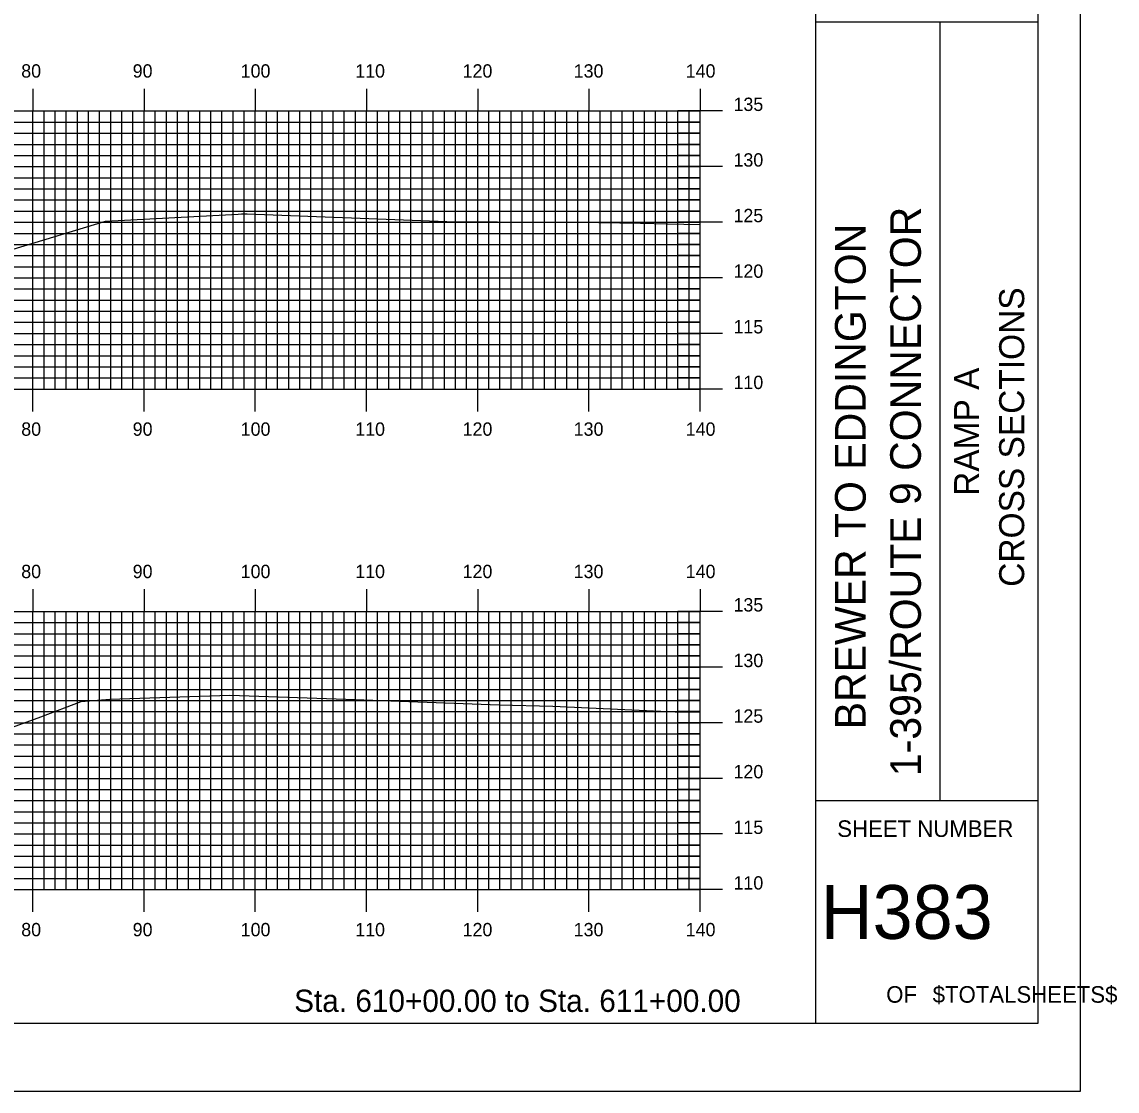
# Model space of a CAD drawing. Extents: x 843356 to 843699, y 363538 to 363758.
# Drawn here: x 843600.4 to 843698.9, y 363537.6 to 363633.7 of the extents above; entities that cross this region are included whole.
import ezdxf

# ---------------------------------------------------------------- set-up
doc = ezdxf.new("R2010")
doc.units = 0
for name, color, linetype in [('BORDER', 7, 'Continuous'), ('H_V ANNOTATION', 7, 'Continuous'), ('MAJOR', 7, 'Continuous'), ('MINOR', 7, 'Continuous'), ('PLOT BOUNDARY', 7, 'Continuous'), ('S_Roadway_Centerline', 7, 'Continuous')]:
    doc.layers.add(name, color=color, linetype=linetype)

msp = doc.modelspace()

# ---------------------------------------------------------------- linework, layer by layer
at = {"layer": 'BORDER'}
for p, q in [((843671.824, 363543.721), (843671.824, 363753.721)), ((843671.824, 363633.727), (843691.824, 363633.727)), ((843683.006, 363563.727), (843683.006, 363633.727)), ((843671.824, 363563.727), (843691.824, 363563.727))]:
    msp.add_line(p, q, dxfattribs=at)
msp.add_lwpolyline([(843371.824, 363543.721), (843691.824, 363543.721), (843691.824, 363753.721), (843371.824, 363753.721)], close=True, dxfattribs=at)
at = {"layer": 'MAJOR'}
for p, q in [((843601.424, 363627.725), (843601.424, 363625.721)), ((843611.424, 363627.725), (843611.424, 363625.721)), ((843621.424, 363627.725), (843621.424, 363625.721)), ((843631.424, 363627.725), (843631.424, 363625.721)), ((843641.424, 363627.725), (843641.424, 363625.721)), ((843651.424, 363627.725), (843651.424, 363625.721)), ((843661.424, 363627.725), (843661.424, 363625.721)), ((843381.424, 363625.721), (843661.424, 363625.721)), ((843381.424, 363625.721), (843661.424, 363625.721)), ((843601.424, 363600.721), (843601.424, 363625.721)), ((843611.424, 363600.721), (843611.424, 363625.721)), ((843621.424, 363600.721), (843621.424, 363625.721)), ((843631.424, 363600.721), (843631.424, 363625.721)), ((843641.424, 363600.721), (843641.424, 363625.721)), ((843651.424, 363600.721), (843651.424, 363625.721)), ((843663.428, 363625.721), (843659.42, 363625.721)), ((843661.424, 363600.721), (843661.424, 363625.721)), ((843661.424, 363600.721), (843661.424, 363625.721)), ((843381.424, 363620.721), (843661.424, 363620.721)), ((843663.428, 363620.721), (843659.42, 363620.721)), ((843381.424, 363615.721), (843661.424, 363615.721)), ((843663.428, 363615.721), (843659.42, 363615.721)), ((843381.424, 363610.721), (843661.424, 363610.721)), ((843663.428, 363610.721), (843659.42, 363610.721)), ((843381.424, 363605.721), (843661.424, 363605.721)), ((843663.428, 363605.721), (843659.42, 363605.721)), ((843381.424, 363600.721), (843661.424, 363600.721)), ((843381.424, 363600.721), (843661.424, 363600.721)), ((843601.424, 363598.717), (843601.424, 363600.721)), ((843611.424, 363598.717), (843611.424, 363600.721)), ((843621.424, 363598.717), (843621.424, 363600.721)), ((843631.424, 363598.717), (843631.424, 363600.721)), ((843641.424, 363598.717), (843641.424, 363600.721)), ((843651.424, 363598.717), (843651.424, 363600.721)), ((843663.428, 363600.721), (843659.42, 363600.721)), ((843661.424, 363598.717), (843661.424, 363600.721)), ((843601.424, 363582.725), (843601.424, 363580.721)), ((843611.424, 363582.725), (843611.424, 363580.721)), ((843621.424, 363582.725), (843621.424, 363580.721)), ((843631.424, 363582.725), (843631.424, 363580.721)), ((843641.424, 363582.725), (843641.424, 363580.721)), ((843651.424, 363582.725), (843651.424, 363580.721)), ((843661.424, 363582.725), (843661.424, 363580.721)), ((843381.424, 363580.721), (843661.424, 363580.721)), ((843381.424, 363580.721), (843661.424, 363580.721)), ((843601.424, 363555.721), (843601.424, 363580.721)), ((843611.424, 363555.721), (843611.424, 363580.721)), ((843621.424, 363555.721), (843621.424, 363580.721)), ((843631.424, 363555.721), (843631.424, 363580.721)), ((843641.424, 363555.721), (843641.424, 363580.721)), ((843651.424, 363555.721), (843651.424, 363580.721)), ((843663.428, 363580.721), (843659.42, 363580.721)), ((843661.424, 363555.721), (843661.424, 363580.721)), ((843661.424, 363555.721), (843661.424, 363580.721)), ((843381.424, 363575.721), (843661.424, 363575.721)), ((843663.428, 363575.721), (843659.42, 363575.721)), ((843381.424, 363570.721), (843661.424, 363570.721)), ((843663.428, 363570.721), (843659.42, 363570.721)), ((843381.424, 363565.721), (843661.424, 363565.721)), ((843663.428, 363565.721), (843659.42, 363565.721)), ((843381.424, 363560.721), (843661.424, 363560.721)), ((843663.428, 363560.721), (843659.42, 363560.721)), ((843381.424, 363555.721), (843661.424, 363555.721)), ((843381.424, 363555.721), (843661.424, 363555.721)), ((843601.424, 363553.717), (843601.424, 363555.721)), ((843611.424, 363553.717), (843611.424, 363555.721)), ((843621.424, 363553.717), (843621.424, 363555.721)), ((843631.424, 363553.717), (843631.424, 363555.721)), ((843641.424, 363553.717), (843641.424, 363555.721)), ((843651.424, 363553.717), (843651.424, 363555.721)), ((843663.428, 363555.721), (843659.42, 363555.721)), ((843661.424, 363553.717), (843661.424, 363555.721))]:
    msp.add_line(p, q, dxfattribs=at)
at = {"layer": 'MINOR'}
for p, q in [((843602.424, 363600.721), (843602.424, 363625.721)), ((843603.424, 363600.721), (843603.424, 363625.721)), ((843604.424, 363600.721), (843604.424, 363625.721)), ((843605.424, 363600.721), (843605.424, 363625.721)), ((843606.424, 363600.721), (843606.424, 363625.721)), ((843607.424, 363600.721), (843607.424, 363625.721)), ((843608.424, 363600.721), (843608.424, 363625.721)), ((843609.424, 363600.721), (843609.424, 363625.721)), ((843610.424, 363600.721), (843610.424, 363625.721)), ((843612.424, 363600.721), (843612.424, 363625.721)), ((843613.424, 363600.721), (843613.424, 363625.721)), ((843614.424, 363600.721), (843614.424, 363625.721)), ((843615.424, 363600.721), (843615.424, 363625.721)), ((843616.424, 363600.721), (843616.424, 363625.721)), ((843617.424, 363600.721), (843617.424, 363625.721)), ((843618.424, 363600.721), (843618.424, 363625.721)), ((843619.424, 363600.721), (843619.424, 363625.721)), ((843620.424, 363600.721), (843620.424, 363625.721)), ((843622.424, 363600.721), (843622.424, 363625.721)), ((843623.424, 363600.721), (843623.424, 363625.721)), ((843624.424, 363600.721), (843624.424, 363625.721)), ((843625.424, 363600.721), (843625.424, 363625.721)), ((843626.424, 363600.721), (843626.424, 363625.721)), ((843627.424, 363600.721), (843627.424, 363625.721)), ((843628.424, 363600.721), (843628.424, 363625.721)), ((843629.424, 363600.721), (843629.424, 363625.721)), ((843630.424, 363600.721), (843630.424, 363625.721)), ((843632.424, 363600.721), (843632.424, 363625.721)), ((843633.424, 363600.721), (843633.424, 363625.721)), ((843634.424, 363600.721), (843634.424, 363625.721)), ((843635.424, 363600.721), (843635.424, 363625.721)), ((843636.424, 363600.721), (843636.424, 363625.721)), ((843637.424, 363600.721), (843637.424, 363625.721)), ((843638.424, 363600.721), (843638.424, 363625.721)), ((843639.424, 363600.721), (843639.424, 363625.721)), ((843640.424, 363600.721), (843640.424, 363625.721)), ((843642.424, 363600.721), (843642.424, 363625.721)), ((843643.424, 363600.721), (843643.424, 363625.721)), ((843644.424, 363600.721), (843644.424, 363625.721)), ((843645.424, 363600.721), (843645.424, 363625.721)), ((843646.424, 363600.721), (843646.424, 363625.721)), ((843647.424, 363600.721), (843647.424, 363625.721)), ((843648.424, 363600.721), (843648.424, 363625.721)), ((843649.424, 363600.721), (843649.424, 363625.721)), ((843650.424, 363600.721), (843650.424, 363625.721)), ((843652.424, 363600.721), (843652.424, 363625.721)), ((843653.424, 363600.721), (843653.424, 363625.721)), ((843654.424, 363600.721), (843654.424, 363625.721)), ((843655.424, 363600.721), (843655.424, 363625.721)), ((843656.424, 363600.721), (843656.424, 363625.721)), ((843657.424, 363600.721), (843657.424, 363625.721)), ((843658.424, 363600.721), (843658.424, 363625.721)), ((843659.424, 363600.721), (843659.424, 363625.721)), ((843660.424, 363600.721), (843660.424, 363625.721)), ((843381.424, 363624.721), (843661.424, 363624.721)), ((843661.424, 363624.721), (843659.42, 363624.721)), ((843381.424, 363623.721), (843661.424, 363623.721)), ((843661.424, 363623.721), (843659.42, 363623.721)), ((843381.424, 363622.721), (843661.424, 363622.721)), ((843661.424, 363622.721), (843659.42, 363622.721)), ((843381.424, 363621.721), (843661.424, 363621.721)), ((843661.424, 363621.721), (843659.42, 363621.721)), ((843381.424, 363619.721), (843661.424, 363619.721)), ((843661.424, 363619.721), (843659.42, 363619.721)), ((843381.424, 363618.721), (843661.424, 363618.721)), ((843661.424, 363618.721), (843659.42, 363618.721)), ((843381.424, 363617.721), (843661.424, 363617.721)), ((843661.424, 363617.721), (843659.42, 363617.721)), ((843381.424, 363616.721), (843661.424, 363616.721)), ((843661.424, 363616.721), (843659.42, 363616.721)), ((843381.424, 363614.721), (843661.424, 363614.721)), ((843661.424, 363614.721), (843659.42, 363614.721)), ((843381.424, 363613.721), (843661.424, 363613.721)), ((843661.424, 363613.721), (843659.42, 363613.721)), ((843381.424, 363612.721), (843661.424, 363612.721)), ((843661.424, 363612.721), (843659.42, 363612.721)), ((843381.424, 363611.721), (843661.424, 363611.721)), ((843661.424, 363611.721), (843659.42, 363611.721)), ((843381.424, 363609.721), (843661.424, 363609.721)), ((843661.424, 363609.721), (843659.42, 363609.721)), ((843381.424, 363608.721), (843661.424, 363608.721)), ((843661.424, 363608.721), (843659.42, 363608.721)), ((843381.424, 363607.721), (843661.424, 363607.721)), ((843661.424, 363607.721), (843659.42, 363607.721)), ((843381.424, 363606.721), (843661.424, 363606.721)), ((843661.424, 363606.721), (843659.42, 363606.721)), ((843381.424, 363604.721), (843661.424, 363604.721)), ((843661.424, 363604.721), (843659.42, 363604.721)), ((843381.424, 363603.721), (843661.424, 363603.721)), ((843661.424, 363603.721), (843659.42, 363603.721)), ((843381.424, 363602.721), (843661.424, 363602.721)), ((843661.424, 363602.721), (843659.42, 363602.721)), ((843381.424, 363601.721), (843661.424, 363601.721)), ((843661.424, 363601.721), (843659.42, 363601.721)), ((843602.424, 363555.721), (843602.424, 363580.721)), ((843603.424, 363555.721), (843603.424, 363580.721)), ((843604.424, 363555.721), (843604.424, 363580.721)), ((843605.424, 363555.721), (843605.424, 363580.721)), ((843606.424, 363555.721), (843606.424, 363580.721)), ((843607.424, 363555.721), (843607.424, 363580.721)), ((843608.424, 363555.721), (843608.424, 363580.721)), ((843609.424, 363555.721), (843609.424, 363580.721)), ((843610.424, 363555.721), (843610.424, 363580.721)), ((843612.424, 363555.721), (843612.424, 363580.721)), ((843613.424, 363555.721), (843613.424, 363580.721)), ((843614.424, 363555.721), (843614.424, 363580.721)), ((843615.424, 363555.721), (843615.424, 363580.721)), ((843616.424, 363555.721), (843616.424, 363580.721)), ((843617.424, 363555.721), (843617.424, 363580.721)), ((843618.424, 363555.721), (843618.424, 363580.721)), ((843619.424, 363555.721), (843619.424, 363580.721)), ((843620.424, 363555.721), (843620.424, 363580.721)), ((843622.424, 363555.721), (843622.424, 363580.721)), ((843623.424, 363555.721), (843623.424, 363580.721)), ((843624.424, 363555.721), (843624.424, 363580.721)), ((843625.424, 363555.721), (843625.424, 363580.721)), ((843626.424, 363555.721), (843626.424, 363580.721)), ((843627.424, 363555.721), (843627.424, 363580.721)), ((843628.424, 363555.721), (843628.424, 363580.721)), ((843629.424, 363555.721), (843629.424, 363580.721)), ((843630.424, 363555.721), (843630.424, 363580.721)), ((843632.424, 363555.721), (843632.424, 363580.721)), ((843633.424, 363555.721), (843633.424, 363580.721)), ((843634.424, 363555.721), (843634.424, 363580.721)), ((843635.424, 363555.721), (843635.424, 363580.721)), ((843636.424, 363555.721), (843636.424, 363580.721)), ((843637.424, 363555.721), (843637.424, 363580.721)), ((843638.424, 363555.721), (843638.424, 363580.721)), ((843639.424, 363555.721), (843639.424, 363580.721)), ((843640.424, 363555.721), (843640.424, 363580.721)), ((843642.424, 363555.721), (843642.424, 363580.721)), ((843643.424, 363555.721), (843643.424, 363580.721)), ((843644.424, 363555.721), (843644.424, 363580.721)), ((843645.424, 363555.721), (843645.424, 363580.721)), ((843646.424, 363555.721), (843646.424, 363580.721)), ((843647.424, 363555.721), (843647.424, 363580.721)), ((843648.424, 363555.721), (843648.424, 363580.721)), ((843649.424, 363555.721), (843649.424, 363580.721)), ((843650.424, 363555.721), (843650.424, 363580.721)), ((843652.424, 363555.721), (843652.424, 363580.721)), ((843653.424, 363555.721), (843653.424, 363580.721)), ((843654.424, 363555.721), (843654.424, 363580.721)), ((843655.424, 363555.721), (843655.424, 363580.721)), ((843656.424, 363555.721), (843656.424, 363580.721)), ((843657.424, 363555.721), (843657.424, 363580.721)), ((843658.424, 363555.721), (843658.424, 363580.721)), ((843659.424, 363555.721), (843659.424, 363580.721)), ((843660.424, 363555.721), (843660.424, 363580.721)), ((843381.424, 363579.721), (843661.424, 363579.721)), ((843661.424, 363579.721), (843659.42, 363579.721)), ((843381.424, 363578.721), (843661.424, 363578.721)), ((843661.424, 363578.721), (843659.42, 363578.721)), ((843381.424, 363577.721), (843661.424, 363577.721)), ((843661.424, 363577.721), (843659.42, 363577.721)), ((843381.424, 363576.721), (843661.424, 363576.721)), ((843661.424, 363576.721), (843659.42, 363576.721)), ((843381.424, 363574.721), (843661.424, 363574.721)), ((843661.424, 363574.721), (843659.42, 363574.721)), ((843381.424, 363573.721), (843661.424, 363573.721)), ((843661.424, 363573.721), (843659.42, 363573.721)), ((843381.424, 363572.721), (843661.424, 363572.721)), ((843661.424, 363572.721), (843659.42, 363572.721)), ((843381.424, 363571.721), (843661.424, 363571.721)), ((843661.424, 363571.721), (843659.42, 363571.721)), ((843381.424, 363569.721), (843661.424, 363569.721)), ((843661.424, 363569.721), (843659.42, 363569.721)), ((843381.424, 363568.721), (843661.424, 363568.721)), ((843661.424, 363568.721), (843659.42, 363568.721)), ((843381.424, 363567.721), (843661.424, 363567.721)), ((843661.424, 363567.721), (843659.42, 363567.721)), ((843381.424, 363566.721), (843661.424, 363566.721)), ((843661.424, 363566.721), (843659.42, 363566.721)), ((843381.424, 363564.721), (843661.424, 363564.721)), ((843661.424, 363564.721), (843659.42, 363564.721)), ((843381.424, 363563.721), (843661.424, 363563.721)), ((843661.424, 363563.721), (843659.42, 363563.721)), ((843381.424, 363562.721), (843661.424, 363562.721)), ((843661.424, 363562.721), (843659.42, 363562.721)), ((843381.424, 363561.721), (843661.424, 363561.721)), ((843661.424, 363561.721), (843659.42, 363561.721)), ((843381.424, 363559.721), (843661.424, 363559.721)), ((843661.424, 363559.721), (843659.42, 363559.721)), ((843381.424, 363558.721), (843661.424, 363558.721)), ((843661.424, 363558.721), (843659.42, 363558.721)), ((843381.424, 363557.721), (843661.424, 363557.721)), ((843661.424, 363557.721), (843659.42, 363557.721)), ((843381.424, 363556.721), (843661.424, 363556.721)), ((843661.424, 363556.721), (843659.42, 363556.721))]:
    msp.add_line(p, q, dxfattribs=at)
at = {"layer": 'PLOT BOUNDARY'}
msp.add_lwpolyline([(843355.638, 363537.603), (843695.638, 363537.603), (843695.638, 363757.603), (843355.638, 363757.603)], close=True, dxfattribs=at)
at = {"layer": 'S_Roadway_Centerline'}
for points in [[(843599.661, 363613.294), (843607.961, 363615.829), (843619.896, 363616.459), (843620.194, 363616.489), (843620.696, 363616.461), (843638.645, 363615.786), (843652.305, 363615.704), (843656.068, 363615.634), (843658.505, 363615.571), (843661.424, 363615.514)], [(843594.124, 363568.35), (843602.151, 363571.244), (843605.774, 363572.615), (843608.349, 363572.848), (843619.14, 363573.185), (843629.572, 363572.852), (843643.359, 363572.333), (843648.173, 363572.221), (843659.175, 363571.705), (843661.424, 363571.656)]]:
    msp.add_lwpolyline(points, dxfattribs=at)

# ---------------------------------------------------------------- texts
at = {"layer": 'BORDER'}
for s, height, p in [('1-395/ROUTE 9 CONNECTOR', 2.75575, (843681.273, 363565.921)), ('BREWER TO EDDINGTON', 2.75575, (843676.313, 363570.13)), ('CROSS SECTIONS', 2.25, (843690.565, 363582.943)), ('RAMP A', 2.25, (843686.515, 363591.118))]:
    msp.add_text(s, height=height, rotation=90, dxfattribs=at).set_placement(p)
for s, height, p in [('SHEET NUMBER', 1.49054, (843673.755, 363560.454)), ('H383', 4.8388, (843672.264, 363551.286)), ('OF', 1.4905, (843678.158, 363545.547)), ('$TOTALSHEETS$', 1.49054, (843682.337, 363545.547))]:
    msp.add_text(s, height=height, dxfattribs=at).set_placement(p)
at = {"layer": 'H_V ANNOTATION'}
for s, height, p in [('80', 1.2, (843600.375, 363628.721)), ('90', 1.2, (843610.397, 363628.721)), ('100', 1.2, (843620.108, 363628.721)), ('110', 1.2, (843630.408, 363628.721)), ('120', 1.2, (843640.065, 363628.721)), ('130', 1.2, (843650.054, 363628.721)), ('140', 1.2, (843660.129, 363628.721)), ('135', 1.2, (843664.424, 363625.721)), ('130', 1.2, (843664.424, 363620.721)), ('125', 1.2, (843664.424, 363615.721)), ('120', 1.2, (843664.424, 363610.721)), ('115', 1.2, (843664.424, 363605.721)), ('110', 1.2, (843664.424, 363600.721)), ('80', 1.2, (843600.375, 363596.521)), ('90', 1.2, (843610.397, 363596.521)), ('100', 1.2, (843620.108, 363596.521)), ('110', 1.2, (843630.408, 363596.521)), ('120', 1.2, (843640.065, 363596.521)), ('130', 1.2, (843650.054, 363596.521)), ('140', 1.2, (843660.129, 363596.521)), ('80', 1.2, (843600.375, 363583.721)), ('90', 1.2, (843610.397, 363583.721)), ('100', 1.2, (843620.108, 363583.721)), ('110', 1.2, (843630.408, 363583.721)), ('120', 1.2, (843640.065, 363583.721)), ('130', 1.2, (843650.054, 363583.721)), ('140', 1.2, (843660.129, 363583.721)), ('135', 1.2, (843664.424, 363580.721)), ('130', 1.2, (843664.424, 363575.721)), ('125', 1.2, (843664.424, 363570.721)), ('120', 1.2, (843664.424, 363565.721)), ('115', 1.2, (843664.424, 363560.721)), ('110', 1.2, (843664.424, 363555.721)), ('80', 1.2, (843600.375, 363551.521)), ('90', 1.2, (843610.397, 363551.521)), ('100', 1.2, (843620.108, 363551.521)), ('110', 1.2, (843630.408, 363551.521)), ('120', 1.2, (843640.065, 363551.521)), ('130', 1.2, (843650.054, 363551.521)), ('140', 1.2, (843660.129, 363551.521)), ('Sta. 610+00.00 to Sta. 611+00.00', 2.0004, (843624.916, 363544.721))]:
    msp.add_text(s, height=height, dxfattribs=at).set_placement(p)

doc.saveas('drawing.dxf')
